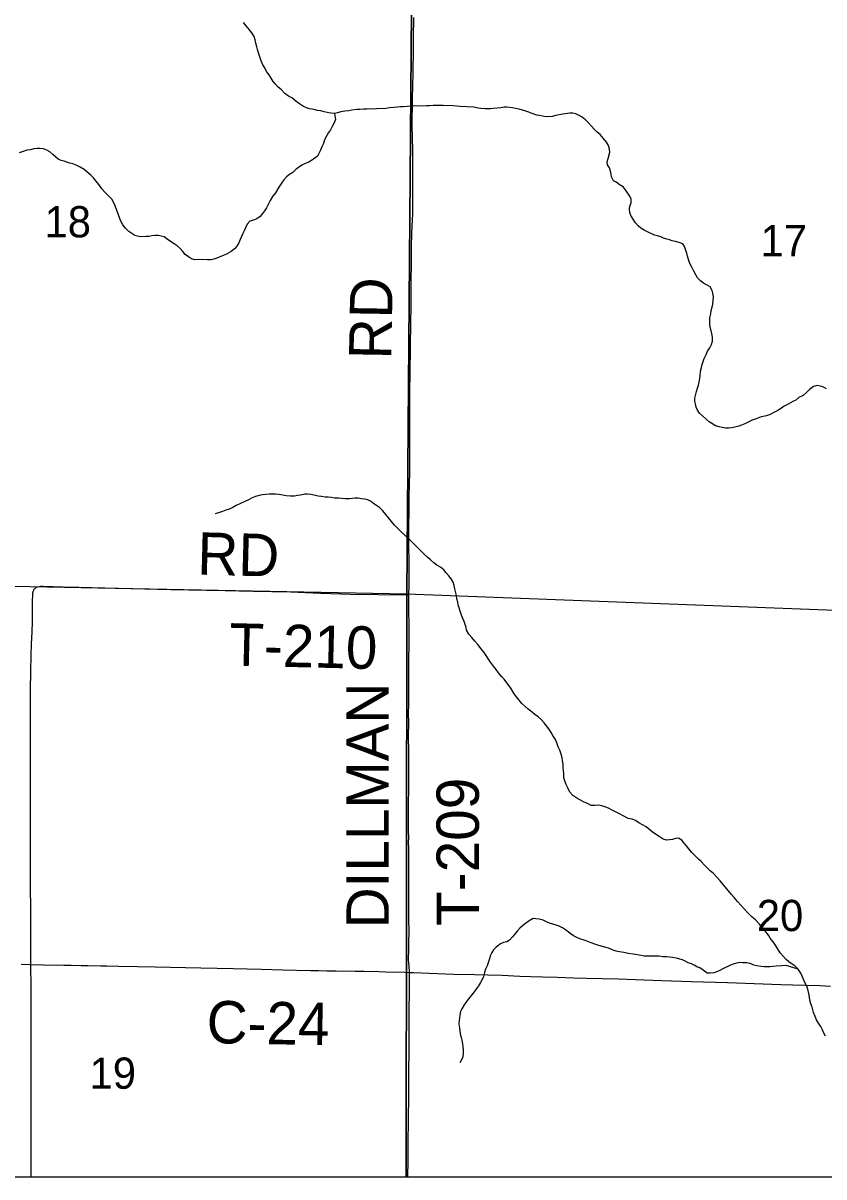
# Model space of a CAD drawing. Extents: x 0 to 34, y 0 to 22.
# Drawn here: x 24.277 to 24.814, y 13.436 to 14.209 of the extents above; entities that cross this region are included whole.
import ezdxf

# ---------------------------------------------------------------- set-up
doc = ezdxf.new("R2010")
doc.units = 0
for name, color, linetype in [('GM_X_County_Road', 7, 'Continuous'), ('GM_X_County_Road_Text', 7, 'Continuous'), ('GM_X_Minor_River', 7, 'Continuous'), ('GM_X_Section', 7, 'Continuous'), ('GM_X_Section_Text', 7, 'Continuous'), ('GM_X_Township_Road', 7, 'Continuous'), ('GM_X_Township_Road_Text', 7, 'Continuous'), ('GM_X_Unincorporated', 7, 'Continuous'), ('SC_Scratch1', 7, 'Continuous'), ('SH_Border', 7, 'Continuous'), ('SH_Cut_Line', 7, 'Continuous')]:
    doc.layers.add(name, color=color, linetype=linetype)

msp = doc.modelspace()

# ---------------------------------------------------------------- linework, layer by layer
at = {"layer": 'GM_X_County_Road'}
msp.add_lwpolyline([(24.27597, 13.57857), (24.28243, 13.57843), (24.29087, 13.57825), (24.30454, 13.57807), (24.3095, 13.57798), (24.316, 13.57786), (24.32066, 13.57777), (24.32934, 13.57759), (24.33337, 13.57747), (24.34114, 13.57729), (24.35387, 13.57707), (24.36566, 13.57683), (24.39637, 13.57615), (24.40724, 13.57596), (24.41811, 13.57571), (24.43672, 13.5753), (24.45132, 13.57496), (24.46995, 13.57453), (24.47523, 13.57437), (24.4808, 13.57423), (24.487, 13.57412), (24.4997, 13.57398), (24.50591, 13.57389), (24.51554, 13.57369), (24.5202, 13.57358), (24.53291, 13.57325), (24.53621, 13.57314), (24.5388, 13.57307), (24.54933, 13.57261), (24.56599, 13.57206), (24.57999, 13.5717), (24.58877, 13.57151), (24.59839, 13.57126), (24.61006, 13.57071), (24.61759, 13.57051), (24.62551, 13.57021), (24.63513, 13.56996), (24.6462, 13.56961), (24.65492, 13.56936), (24.66529, 13.56916), (24.67631, 13.56877), (24.68767, 13.56832), (24.70506, 13.56773), (24.72523, 13.56701), (24.74945, 13.56636), (24.78514, 13.56508), (24.80133, 13.56463), (24.81122, 13.56427), (24.81835, 13.56396)], dxfattribs=at)
at = {"layer": 'GM_X_Minor_River'}
for points in [[(24.47676, 14.15035), (24.47449, 14.15062), (24.47204, 14.15128), (24.46921, 14.15176), (24.46714, 14.15241), (24.46508, 14.15324), (24.46248, 14.15505), (24.46008, 14.15685), (24.4573, 14.15904), (24.45507, 14.16026), (24.45266, 14.16206), (24.45009, 14.16462), (24.44825, 14.16621), (24.44642, 14.16818), (24.44478, 14.17014), (24.44352, 14.17228), (24.44208, 14.17442), (24.44026, 14.17677), (24.43921, 14.17909), (24.43795, 14.18123), (24.43672, 14.18393), (24.43603, 14.18586), (24.43518, 14.18855), (24.43433, 14.19144), (24.43383, 14.19336), (24.43315, 14.19567), (24.43266, 14.19797), (24.43198, 14.20008), (24.43055, 14.20261), (24.42892, 14.20476), (24.42673, 14.20731), (24.42491, 14.20966)], [(24.48582, 14.14869), (24.48663, 14.14467), (24.4856, 14.14243), (24.48437, 14.14), (24.48315, 14.13776), (24.48194, 14.1359), (24.48073, 14.13385), (24.47929, 14.13086), (24.47845, 14.12861), (24.47742, 14.12636), (24.47658, 14.12411), (24.47575, 14.12224), (24.47453, 14.12), (24.4712, 14.11746), (24.46868, 14.11602), (24.46637, 14.11516), (24.46404, 14.11391), (24.46015, 14.11139), (24.45798, 14.10918), (24.45584, 14.10774), (24.45369, 14.1061), (24.4519, 14.10407), (24.4503, 14.10185), (24.44869, 14.09924), (24.44627, 14.09553), (24.44447, 14.09293), (24.44285, 14.09032), (24.44142, 14.08752), (24.4404, 14.08547), (24.43899, 14.08342), (24.4376, 14.08157), (24.436, 14.07954), (24.43386, 14.07809), (24.43174, 14.07722), (24.42924, 14.07636), (24.42746, 14.07452), (24.42623, 14.07209), (24.4254, 14.07003), (24.42457, 14.06816), (24.42354, 14.0661), (24.42272, 14.06423), (24.42169, 14.06198), (24.42046, 14.05974), (24.41888, 14.0579), (24.41672, 14.05608), (24.41362, 14.05429), (24.4113, 14.05342), (24.40706, 14.05167), (24.40513, 14.05098), (24.40322, 14.05066), (24.40074, 14.05056), (24.39448, 14.05079), (24.39238, 14.05067), (24.39012, 14.05113), (24.38808, 14.05254), (24.38586, 14.05414), (24.38422, 14.0561), (24.38239, 14.05826), (24.38036, 14.05985), (24.37851, 14.06125), (24.3761, 14.06286), (24.37387, 14.06446), (24.37164, 14.06587), (24.36976, 14.06651), (24.36788, 14.06696), (24.36559, 14.06685), (24.36349, 14.06655), (24.36158, 14.06624), (24.35949, 14.06612), (24.35587, 14.06606), (24.35398, 14.06632), (24.3521, 14.06696), (24.35006, 14.06817), (24.34802, 14.06958), (24.34581, 14.07175), (24.344, 14.07409), (24.34239, 14.07701), (24.3417, 14.07893), (24.33996, 14.08356), (24.33894, 14.08683), (24.33806, 14.08876), (24.33662, 14.0911), (24.33443, 14.09346), (24.33223, 14.09563), (24.33004, 14.09818), (24.32805, 14.10111), (24.32604, 14.10346), (24.3244, 14.10542), (24.32257, 14.1072), (24.31999, 14.10957), (24.31815, 14.11116), (24.31554, 14.11259), (24.31274, 14.11402), (24.31049, 14.11486), (24.3086, 14.11531), (24.30654, 14.11595), (24.30466, 14.11659), (24.30277, 14.11704), (24.30072, 14.11806), (24.29887, 14.11946), (24.29703, 14.12124)], [(24.69586, 14.06925), (24.69343, 14.07048), (24.69138, 14.0717), (24.68954, 14.07328), (24.68771, 14.07525), (24.68609, 14.07778), (24.68466, 14.08031), (24.68397, 14.08223), (24.68367, 14.08453), (24.68393, 14.08642), (24.68477, 14.08867), (24.68486, 14.09114), (24.68399, 14.09327), (24.6811, 14.09755), (24.67946, 14.09951), (24.67686, 14.10113), (24.67482, 14.10253), (24.67295, 14.10355), (24.67152, 14.10608), (24.6714, 14.10798), (24.6709, 14.1099), (24.67022, 14.11221), (24.66896, 14.11416), (24.66866, 14.11626), (24.66931, 14.11852), (24.6706, 14.12266), (24.67029, 14.12476), (24.66962, 14.12707), (24.66837, 14.12939), (24.66617, 14.13176), (24.66399, 14.1345), (24.66196, 14.13609), (24.65994, 14.13807), (24.6583, 14.14003), (24.6561, 14.14239), (24.65427, 14.14436), (24.65187, 14.14615), (24.65001, 14.14736), (24.64776, 14.14839), (24.64569, 14.14885), (24.64359, 14.14873), (24.63901, 14.14814), (24.63423, 14.14736), (24.63193, 14.14668), (24.62774, 14.14645), (24.62546, 14.14672), (24.62339, 14.14718), (24.6215, 14.14743), (24.6185, 14.14868), (24.61625, 14.14952), (24.61418, 14.15017), (24.60967, 14.15147), (24.60721, 14.15194), (24.60533, 14.15239), (24.60155, 14.15291), (24.59964, 14.15278), (24.59734, 14.1523), (24.59487, 14.15219), (24.59239, 14.1519), (24.59048, 14.15178), (24.58858, 14.15166), (24.58668, 14.15173), (24.58403, 14.15201), (24.58213, 14.15227), (24.57931, 14.15294), (24.5702, 14.15327), (24.56792, 14.15354), (24.56546, 14.15382), (24.55882, 14.15406), (24.55691, 14.15394), (24.55445, 14.15403), (24.55197, 14.15393), (24.54969, 14.15382), (24.54759, 14.1537), (24.54473, 14.15343), (24.53866, 14.15364), (24.53656, 14.15353), (24.53465, 14.15322), (24.53217, 14.15312), (24.53027, 14.15299), (24.52817, 14.15288), (24.52569, 14.15259), (24.52283, 14.15231), (24.52035, 14.15202), (24.51406, 14.15167), (24.51159, 14.15157), (24.5095, 14.15165), (24.5076, 14.15153), (24.50531, 14.15142), (24.50284, 14.15132), (24.50093, 14.15119), (24.49749, 14.15075), (24.49558, 14.15044), (24.49291, 14.15015), (24.49023, 14.14968), (24.48793, 14.149), (24.48582, 14.14869), (24.48355, 14.14878), (24.48109, 14.14924), (24.47902, 14.1497), (24.47676, 14.15035)], [(24.29703, 14.12124), (24.29519, 14.12283), (24.29314, 14.12404), (24.29089, 14.12488), (24.28843, 14.12516), (24.28652, 14.12504), (24.28443, 14.12493), (24.28193, 14.12425), (24.27964, 14.12396), (24.27733, 14.12309), (24.27445, 14.12224)], [(24.81581, 13.96414), (24.81339, 13.96556), (24.81151, 13.96601), (24.80943, 13.96627), (24.80694, 13.96579), (24.80439, 13.9636), (24.80222, 13.9614), (24.80006, 13.95957), (24.79717, 13.95835), (24.7952, 13.95651), (24.79308, 13.95564), (24.78997, 13.95385), (24.78746, 13.95261), (24.7855, 13.95115), (24.78317, 13.94972), (24.78085, 13.94847), (24.77755, 13.94669), (24.77448, 13.94584), (24.77199, 13.94536), (24.76852, 13.94397), (24.76602, 13.9431), (24.76408, 13.94222), (24.76098, 13.94062), (24.75886, 13.93975), (24.75694, 13.93906), (24.75425, 13.93839), (24.75214, 13.9379), (24.75024, 13.93777), (24.74815, 13.93785), (24.74588, 13.93812), (24.7438, 13.93858), (24.74136, 13.93942), (24.73894, 13.94084), (24.73709, 13.94205), (24.73506, 13.94383), (24.73267, 13.94601), (24.73064, 13.9478), (24.7292, 13.94994), (24.72832, 13.95187), (24.72782, 13.95398), (24.72751, 13.9559), (24.72758, 13.9578), (24.7285, 13.96233), (24.72934, 13.96458), (24.72999, 13.96665), (24.73067, 13.96967), (24.73097, 13.97289), (24.73127, 13.97592), (24.73193, 13.97837), (24.73239, 13.98045), (24.73303, 13.98252), (24.73367, 13.9844), (24.7351, 13.9872), (24.73593, 13.98926), (24.73754, 13.99149), (24.73857, 13.99373), (24.73941, 13.99598), (24.73931, 13.99865), (24.73883, 14.00114), (24.73833, 14.00306), (24.73784, 14.00536), (24.73754, 14.00746), (24.73743, 14.00975), (24.7375, 14.01165), (24.73817, 14.01429), (24.73844, 14.01656), (24.73909, 14.01882), (24.73954, 14.0209), (24.73982, 14.02336), (24.73991, 14.02583), (24.73962, 14.02812), (24.73911, 14.03004), (24.73768, 14.03237), (24.73526, 14.03379), (24.7332, 14.03482), (24.73117, 14.03641), (24.72935, 14.03857), (24.72809, 14.04052), (24.72685, 14.04304), (24.72542, 14.04556), (24.72418, 14.04808), (24.72349, 14.05019), (24.72246, 14.05308), (24.72214, 14.055), (24.72128, 14.0575), (24.72059, 14.05943), (24.71952, 14.06137), (24.71708, 14.06222), (24.71463, 14.06287), (24.71237, 14.06334), (24.71049, 14.06397), (24.70861, 14.06442), (24.70654, 14.06507), (24.70467, 14.06589), (24.70241, 14.06655), (24.70034, 14.06719), (24.69586, 14.06925)], [(24.55033, 13.84966), (24.54848, 13.85105), (24.54627, 13.85304), (24.54426, 13.8552), (24.54242, 13.85698), (24.5404, 13.85895), (24.53783, 13.86152), (24.53545, 13.86389), (24.53324, 13.86587), (24.53066, 13.86824), (24.52809, 13.87081), (24.52626, 13.87278), (24.52407, 13.87533), (24.52225, 13.87748), (24.52043, 13.87983), (24.51824, 13.88238), (24.51604, 13.88456), (24.51419, 13.88595), (24.51233, 13.88716), (24.51012, 13.88895), (24.50825, 13.88978), (24.50598, 13.89024), (24.50409, 13.8905), (24.50182, 13.89077), (24.49973, 13.89085), (24.49783, 13.89073), (24.49591, 13.89041), (24.49306, 13.89033), (24.49079, 13.8906), (24.48871, 13.89086), (24.48586, 13.89097), (24.48397, 13.89122), (24.4817, 13.8915), (24.47961, 13.89157), (24.47715, 13.89204), (24.47507, 13.8923), (24.47319, 13.89275), (24.47016, 13.89324), (24.46789, 13.89351), (24.46599, 13.89358), (24.46312, 13.89292), (24.46102, 13.89262), (24.45911, 13.89231), (24.45644, 13.89221), (24.4536, 13.89251), (24.45134, 13.89297), (24.44869, 13.89325), (24.44641, 13.89352), (24.44433, 13.8936), (24.44204, 13.89349), (24.43957, 13.89339), (24.43765, 13.89308), (24.43554, 13.89258), (24.43305, 13.89191), (24.43074, 13.89104), (24.42822, 13.8898), (24.4259, 13.88856), (24.4201, 13.88591), (24.41777, 13.88466), (24.41526, 13.88361), (24.41314, 13.88274), (24.41083, 13.88187), (24.40814, 13.88101), (24.40602, 13.88033)], [(24.72191, 13.65785), (24.72027, 13.65982), (24.71882, 13.66177), (24.71659, 13.66318), (24.71449, 13.66288), (24.71256, 13.66219), (24.71046, 13.66188), (24.70856, 13.66176), (24.7063, 13.66241), (24.70351, 13.66422), (24.7011, 13.66583), (24.69888, 13.66743), (24.69481, 13.67062), (24.68997, 13.67346), (24.68774, 13.67487), (24.68549, 13.67571), (24.68285, 13.67637), (24.67986, 13.67781), (24.67651, 13.67965), (24.67389, 13.68088), (24.67203, 13.6819), (24.6696, 13.68313), (24.66773, 13.68395), (24.6651, 13.68481), (24.66283, 13.68527), (24.66035, 13.68498), (24.65807, 13.68506), (24.65602, 13.68609), (24.65284, 13.68753), (24.65041, 13.68876), (24.64836, 13.68979), (24.64577, 13.69178), (24.64376, 13.69395), (24.64234, 13.69685), (24.64111, 13.69956), (24.64042, 13.70148), (24.63973, 13.7036), (24.63963, 13.70608), (24.63953, 13.70836), (24.63921, 13.71028), (24.63911, 13.71275), (24.63882, 13.71505), (24.6385, 13.71696), (24.63783, 13.71946), (24.63697, 13.72196), (24.63592, 13.72428), (24.63487, 13.72698), (24.63401, 13.72929), (24.63239, 13.73182), (24.63113, 13.73396), (24.62951, 13.7363), (24.62806, 13.73826), (24.62642, 13.74041), (24.62478, 13.74237), (24.62257, 13.74435), (24.62016, 13.74596), (24.61758, 13.74814), (24.61573, 13.74954), (24.61352, 13.75152), (24.61149, 13.75331), (24.60876, 13.75664), (24.60694, 13.75899), (24.60568, 13.76093), (24.60407, 13.76365), (24.59972, 13.76952), (24.59789, 13.77149), (24.59588, 13.77384), (24.59425, 13.77599), (24.59243, 13.77834), (24.59044, 13.78107), (24.58918, 13.78302), (24.58756, 13.78555), (24.5863, 13.7875), (24.5843, 13.79004), (24.58193, 13.79279), (24.58011, 13.79514), (24.57792, 13.7975), (24.57591, 13.79986), (24.57448, 13.80238), (24.57417, 13.80429), (24.57279, 13.80815), (24.57191, 13.81027), (24.57105, 13.81258), (24.57019, 13.81509), (24.56951, 13.81739), (24.56882, 13.81932), (24.56851, 13.82123), (24.56802, 13.82353), (24.56772, 13.82564), (24.56721, 13.82756), (24.56655, 13.83024), (24.56606, 13.83235), (24.56538, 13.83466), (24.56412, 13.8368), (24.56267, 13.83875), (24.56085, 13.84091), (24.55921, 13.84287), (24.55699, 13.84466), (24.55458, 13.84608), (24.55253, 13.84749), (24.55033, 13.84966)], [(24.81503, 13.5305), (24.81378, 13.53283), (24.81309, 13.53475), (24.81202, 13.53688), (24.8104, 13.53922), (24.80914, 13.54136), (24.80809, 13.54368), (24.80704, 13.54638), (24.80603, 13.54984), (24.80516, 13.55216), (24.80467, 13.55446), (24.80437, 13.55656), (24.80389, 13.55905), (24.80323, 13.56193), (24.80255, 13.56404), (24.8013, 13.56637), (24.79936, 13.57062), (24.79849, 13.57275), (24.79668, 13.57529), (24.79485, 13.57725), (24.79262, 13.57866), (24.79059, 13.58026), (24.78874, 13.58185), (24.78673, 13.58401), (24.78472, 13.58637), (24.7822, 13.59026), (24.78058, 13.59279), (24.77804, 13.59611), (24.77678, 13.59806), (24.77442, 13.60119), (24.77259, 13.60316), (24.77078, 13.60551), (24.76822, 13.60826), (24.76601, 13.61024), (24.76306, 13.61301), (24.7605, 13.61577), (24.75849, 13.61793), (24.75612, 13.62068), (24.75394, 13.62342), (24.75211, 13.62539), (24.7501, 13.62774), (24.74645, 13.63206), (24.74445, 13.63441), (24.74226, 13.63696), (24.74006, 13.63932), (24.73785, 13.6413), (24.73583, 13.64328), (24.734, 13.64506), (24.7318, 13.64742), (24.72996, 13.64901), (24.72758, 13.65156), (24.72556, 13.65354), (24.72336, 13.6559), (24.72191, 13.65785)], [(24.79668, 13.57529), (24.78879, 13.57785), (24.78574, 13.57758), (24.78193, 13.57734), (24.77983, 13.57703), (24.77773, 13.57692), (24.77583, 13.57679), (24.77393, 13.57686), (24.77185, 13.57713), (24.76901, 13.57761), (24.76713, 13.57806), (24.76451, 13.5791), (24.76224, 13.57956), (24.75977, 13.57965), (24.75768, 13.57973), (24.75539, 13.57943), (24.75328, 13.57874), (24.75135, 13.57805), (24.74632, 13.57557), (24.74419, 13.5745), (24.74226, 13.57362), (24.74014, 13.57294), (24.73785, 13.57264), (24.73576, 13.57271), (24.73298, 13.57472), (24.73075, 13.57613), (24.72888, 13.57695), (24.72702, 13.57797), (24.72515, 13.5788), (24.72309, 13.57963), (24.72103, 13.58066), (24.71916, 13.58149), (24.71503, 13.58278), (24.71257, 13.58306), (24.70859, 13.58358), (24.70613, 13.58367), (24.70347, 13.58395), (24.69854, 13.58413), (24.69625, 13.58402), (24.6936, 13.58412), (24.69152, 13.58438), (24.68887, 13.58486), (24.68623, 13.58533), (24.68282, 13.58583), (24.67981, 13.58651), (24.67697, 13.587), (24.67471, 13.58746), (24.67264, 13.5881), (24.66965, 13.58935), (24.66776, 13.5898), (24.66569, 13.59044), (24.66306, 13.59111), (24.66043, 13.59215), (24.65799, 13.593), (24.65574, 13.59384), (24.6533, 13.59469), (24.65048, 13.59555), (24.64843, 13.59658), (24.64618, 13.59761), (24.64396, 13.59921), (24.64156, 13.6012), (24.63877, 13.60301), (24.63653, 13.60404), (24.63446, 13.60469), (24.63221, 13.60553), (24.62995, 13.60618), (24.62771, 13.60721), (24.62584, 13.60804), (24.6232, 13.60871), (24.62093, 13.60898), (24.61904, 13.60924), (24.61652, 13.60781), (24.61397, 13.60581), (24.61202, 13.60435), (24.61006, 13.60271), (24.60828, 13.60087), (24.60668, 13.59865), (24.6051, 13.5968), (24.60331, 13.59477), (24.60137, 13.5937), (24.59926, 13.59321), (24.59714, 13.59233), (24.59421, 13.59016), (24.59244, 13.58832), (24.59142, 13.58645), (24.59039, 13.58421), (24.58974, 13.58214), (24.58889, 13.5795), (24.58825, 13.57763), (24.58722, 13.57538), (24.58657, 13.57312), (24.58571, 13.57049), (24.58488, 13.56843), (24.58385, 13.56637), (24.58244, 13.56414), (24.58104, 13.56229), (24.57964, 13.56024), (24.57784, 13.55784), (24.57605, 13.55562), (24.57446, 13.55358), (24.57286, 13.55136)], [(24.57286, 13.55136), (24.57124, 13.54875), (24.57041, 13.54688), (24.56995, 13.54461), (24.56944, 13.54102), (24.56936, 13.53874), (24.56965, 13.53606), (24.56995, 13.53396), (24.57026, 13.53205), (24.57093, 13.52955), (24.57124, 13.52764), (24.57173, 13.52534), (24.57204, 13.52343), (24.57215, 13.52114), (24.57226, 13.51904), (24.57198, 13.51658), (24.57096, 13.51452), (24.56994, 13.51247)]]:
    msp.add_lwpolyline(points, dxfattribs=at)
at = {"layer": 'GM_X_Section'}
for points in [[(24.08356, 14.33844), (24.53855, 14.33027), (24.53442, 13.82651), (24.07452, 13.83559)], [(24.53855, 14.33027), (25.03984, 14.31055), (25.03876, 13.80745), (24.53442, 13.82651)]]:
    msp.add_lwpolyline(points, close=True, dxfattribs=at)
at = {"layer": 'GM_X_Township_Road'}
for points in [[(24.53621, 13.57314), (24.5359, 13.57762), (24.53574, 13.57948), (24.53563, 13.5814), (24.53558, 13.58306), (24.53565, 13.58705), (24.53587, 13.59322), (24.53591, 13.60066), (24.53582, 13.60874), (24.53583, 13.61464), (24.53579, 13.62054), (24.53576, 13.62704), (24.53585, 13.63137), (24.53586, 13.63382), (24.53582, 13.6384), (24.53579, 13.64175), (24.5358, 13.64483), (24.53578, 13.64981), (24.53572, 13.65382), (24.53572, 13.65439), (24.53571, 13.65531), (24.53582, 13.65688), (24.53575, 13.65714), (24.53565, 13.65801), (24.53563, 13.65832), (24.53561, 13.65862), (24.53562, 13.66011), (24.53566, 13.66352), (24.53561, 13.66788), (24.53556, 13.67253), (24.53554, 13.67873), (24.53557, 13.68554), (24.53564, 13.68989), (24.53566, 13.69206), (24.53569, 13.69393), (24.5357, 13.69579), (24.5357, 13.70231), (24.5357, 13.72187), (24.53561, 13.73025), (24.53565, 13.74174), (24.53564, 13.74546), (24.53568, 13.75354), (24.53573, 13.76751), (24.53582, 13.78366), (24.53588, 13.79205), (24.5359, 13.7992), (24.53588, 13.80386), (24.53583, 13.81813), (24.53586, 13.82599), (24.53589, 13.83242), (24.53592, 13.83956), (24.53593, 13.84795), (24.53584, 13.85913), (24.53585, 13.87249), (24.53595, 13.8818), (24.53609, 13.89204), (24.53633, 13.90848), (24.53637, 13.91345), (24.5364, 13.91842), (24.53633, 13.92246), (24.53635, 13.92867), (24.53639, 13.94109), (24.5365, 13.96251), (24.53671, 13.97461), (24.53697, 13.992), (24.53717, 14.00877), (24.53726, 14.01902), (24.53727, 14.02957), (24.53739, 14.03609), (24.53757, 14.0482), (24.53761, 14.05938), (24.53778, 14.06807), (24.53797, 14.07303), (24.53835, 14.08141), (24.53839, 14.08608), (24.53835, 14.08979), (24.53846, 14.09879), (24.53845, 14.11305), (24.53834, 14.12391), (24.53819, 14.1326), (24.53809, 14.14036), (24.5383, 14.15837), (24.53845, 14.16706), (24.53862, 14.17573), (24.53887, 14.19248), (24.53898, 14.1993), (24.53917, 14.21297)], [(24.28243, 13.57843), (24.28242, 13.58737), (24.28236, 13.59762), (24.2823, 13.60787), (24.28212, 13.638), (24.2821, 13.65518), (24.2821, 13.66142), (24.2821, 13.67061), (24.28212, 13.69794), (24.28216, 13.72512), (24.28215, 13.74484), (24.28214, 13.75407), (24.28221, 13.76222), (24.28226, 13.7749), (24.2825, 13.78573), (24.28283, 13.79326), (24.28334, 13.80101), (24.28353, 13.80814), (24.28354, 13.82274), (24.28363, 13.82532), (24.28372, 13.82696), (24.28377, 13.82744), (24.28388, 13.82804), (24.28397, 13.82848), (24.28409, 13.82887), (24.28427, 13.82928), (24.28448, 13.82963), (24.28471, 13.82996), (24.28494, 13.83026), (24.28528, 13.83062), (24.28562, 13.83092), (24.28584, 13.83107), (24.28625, 13.83132), (24.28682, 13.83155), (24.28777, 13.83179), (24.28889, 13.83189), (24.29072, 13.8319), (24.30405, 13.83155), (24.31444, 13.8312), (24.3497, 13.83034), (24.3673, 13.82992), (24.37631, 13.82978), (24.40022, 13.82929), (24.41264, 13.82908), (24.43133, 13.82858), (24.45642, 13.82822), (24.47659, 13.82731), (24.4905, 13.82681), (24.49652, 13.82666), (24.51492, 13.8263), (24.5342, 13.82602), (24.53586, 13.82599)], [(24.28259, 13.43613), (24.2826, 13.44604), (24.28252, 13.46933), (24.28261, 13.483), (24.28268, 13.4917), (24.28253, 13.50443), (24.28256, 13.52431), (24.28251, 13.5473), (24.28248, 13.56594), (24.28243, 13.57526), (24.28243, 13.57843)], [(24.53511, 13.43613), (24.53522, 13.44704), (24.53535, 13.4604), (24.53546, 13.47282), (24.53569, 13.49237), (24.53583, 13.50293), (24.53607, 13.52467), (24.53609, 13.54614), (24.5361, 13.56195), (24.5362, 13.57199), (24.53621, 13.57314)]]:
    msp.add_lwpolyline(points, dxfattribs=at)
at = {"layer": 'GM_X_Unincorporated'}
for points in [[(24.06613, 13.43613), (24.53388, 13.43613), (24.53442, 13.82651), (24.07452, 13.83559), (24.07424, 13.83162)], [(24.53388, 13.43613), (25.0365, 13.43613), (25.03876, 13.80745), (24.53442, 13.82651)]]:
    msp.add_lwpolyline(points, close=True, dxfattribs=at)
at = {"layer": 'SC_Scratch1'}
msp.add_line((1.5, 13.43613), (32, 13.43613), dxfattribs=at)
msp.add_lwpolyline([(24.08615, 14.33912), (24.08197, 14.12959), (24.07963, 14.01235), (24.07597, 13.82883), (24.07329, 13.6948), (24.07326, 13.69312), (24.07124, 13.5822), (24.06692, 13.43613), (27.02715, 13.43613)], dxfattribs=at)
at = {"layer": 'SH_Border'}
msp.add_lwpolyline([(23.89999, 20.23613), (23.89999, 13.43613), (30.69999, 13.43613), (30.69999, 20.23613)], close=True, dxfattribs=at)
at = {"layer": 'SH_Cut_Line'}
msp.add_lwpolyline([(23.89999, 20.23613), (23.89999, 13.43613), (30.0382, 13.43613)], dxfattribs=at)

# ---------------------------------------------------------------- texts
at = {"layer": 'GM_X_County_Road_Text'}
msp.add_text('C-24', height=0.028409, rotation=358.97075, dxfattribs=at).set_placement((24.40003, 13.52581))
at = {"layer": 'GM_X_Section_Text'}
for s, p in [('18', (24.29154, 14.06561)), ('17', (24.77154, 14.05296)), ('20', (24.76904, 13.60082)), ('19', (24.32175, 13.4952))]:
    msp.add_text(s, height=0.020928, rotation=0.00001, dxfattribs=at).set_placement(p)
at = {"layer": 'GM_X_Township_Road_Text'}
for s, rotation, p in [('RD', 89.0123, (24.52402, 13.98369)), ('RD', 358.51936, (24.39371, 13.83967)), ('T-210', 358.5962, (24.41513, 13.77879)), ('DILLMAN', 90, (24.52234, 13.60266)), ('T-209', 90, (24.58273, 13.60433))]:
    msp.add_text(s, height=0.028409, rotation=rotation, dxfattribs=at).set_placement(p)

doc.saveas('drawing.dxf')
